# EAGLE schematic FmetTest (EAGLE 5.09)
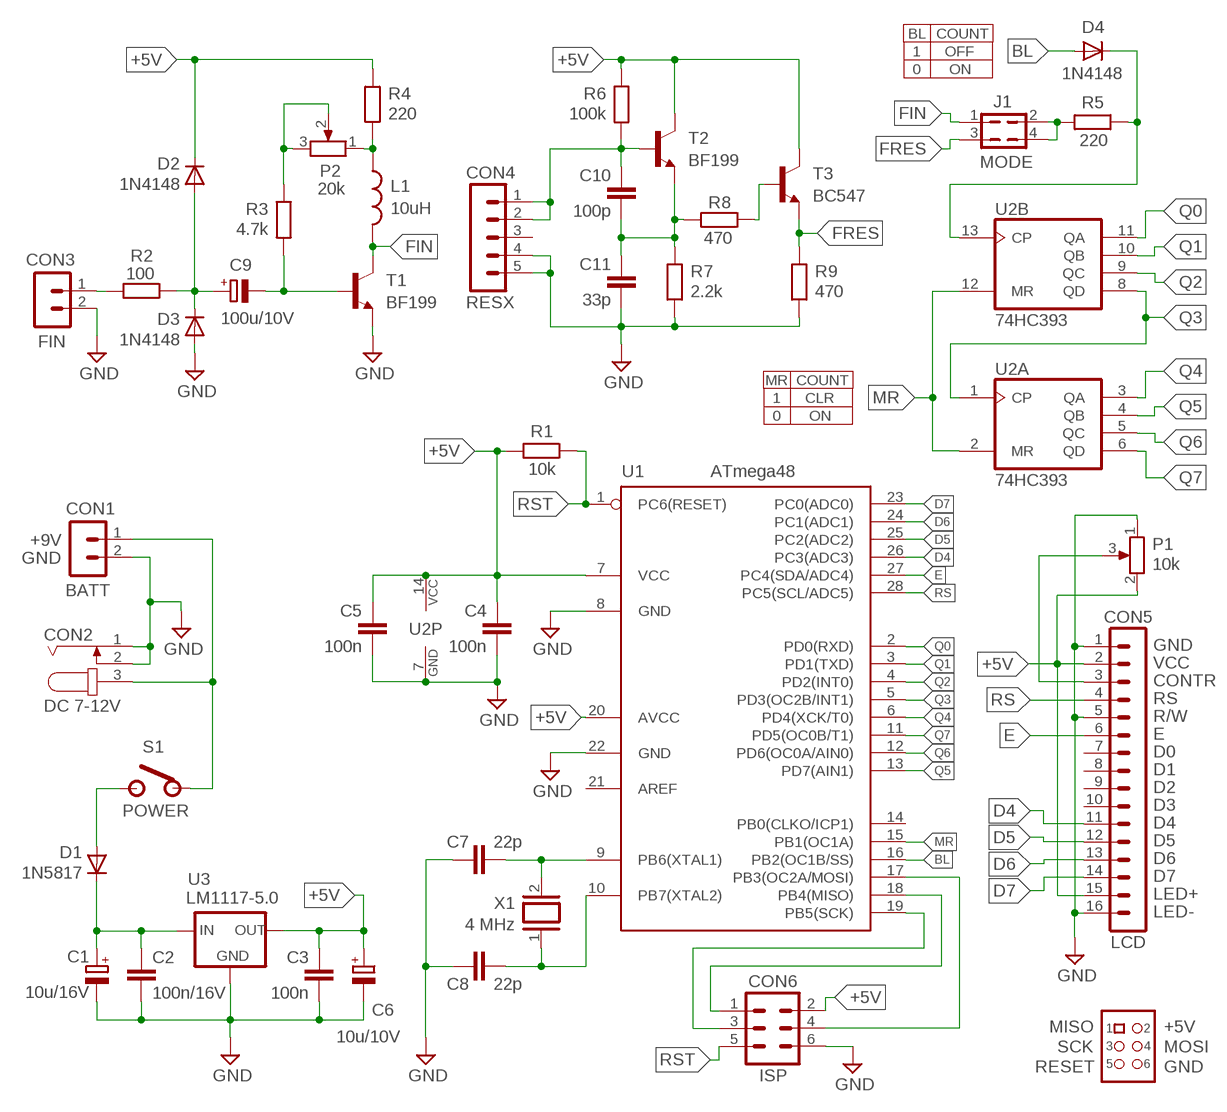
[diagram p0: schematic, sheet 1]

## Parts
C1  10u/16V  C5/2.5  [C5/2.5]
C2  100n/16V  C5-025X075  [C5-025X075]
C3  100n  C5-025X075  [C5-025X075]
C4  100n  C5-025X075  [C5-025X075]
C5  100n  C5-025X075  [C5-025X075]
C6  10u/10V  C5/2.5  [C5/2.5]
C7  22p  C5-025X075  [C5-025X075]
C8  22p  C5-025X075  [C5-025X075]
C9  100u/10V  C7/2.5  [C7/2.5]
C10  100p  C5-025X075  [C5-025X075]
C11  33p  C5-025X075  [C5-025X075]
CON1  BATT  CON-2PIN  [CON-2PIN]
CON2  DC 7-12V  DC-JACK  [DC-JACK]
CON3  FIN  CON-2PIN  [CON-2PIN]
CON4  RESX  CON-5X1  [CON-5X1]
CON5  LCD  CON-16X1  [CON-16X1]
CON6  ISP  CON-3X2  [CON-3X2]
D1  1N5817  PAD-D7.5N  [D-7.5]
D2  1N4148  PAD-D7.5S  [D-7]
D3  1N4148  PAD-D7.5S  [D-7]
D4  1N4148  PAD-D7.5S  [D-7]
J1  MODE  J-2X2  [J-2X2]
L1  10uH  L5L7  [L7]
P1  10k  POT5X5V  [POT5X5V]
P2  20k  P-HELITRIM  [P-HV]
R1  10k  R10R7  [R7]
R2  100  R10R7  [R7]
R3  4.7k  R10R7  [R7]
R4  220  R10R7  [R7]
R5  220  R10R7  [R7]
R6  100k  R10R7  [R7]
R7  2.2k  R10R7  [R7]
R8  470  R10R7  [R7]
R9  470  R10R7  [R7]
S1  POWER  SW2A  [CON-2PIN]
T1  BF199  [TO92-CEB]
T2  BF199  [TO92-CEB]
T3  BC547  [TO92-CBE]
U1  ATmega48  ATMEGA48  [DIP28]
U2  74HC393  74393  [DIP14]
U3  LM1117-5.0  LM1117-FIX  [SOT223]
X1  4 MHz  XTAL  [XTAL]

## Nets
+5V: C3.1 C4.1 C5.1 C6.+ CON5.2 CON5.15 CON6.2 D2.C P1.2 R1.1 R4.2 R6.2 T2.C T3.C U1.7(VCC) U1.20(AVCC) U2.14(P:VCC) U3.2(OUT)
BL: D4.A
D4: CON5.11 U1.26(PC3(ADC3))
D5: CON5.12 U1.25(PC2(ADC2))
D6: CON5.13 U1.24(PC1(ADC1))
D7: CON5.14 U1.23(PC0(ADC0))
E: CON5.6 U1.27(PC4(SDA/ADC4))
FIN: J1.1 L1.2 T1.C
FRES: J1.3 R9.2 T3.E
GND: C1.- C2.2 C3.2 C4.2 C5.2 C6.- C7.1 C8.1 C11.2 CON1.2 CON2.1 CON2.2 CON3.2 CON4.4 CON4.5 CON5.1 CON5.5 CON5.16 CON6.6 D3.A P1.1 R7.1 R9.1 T1.E U1.8(GND) U1.22(GND) U2.7(P:GND) U3.1(GND)
MR: U2.2(A:MR) U2.12(B:MR)
N$1: D1.A S1.1
N$3: CON3.1 R2.1
N$4: C7.2 U1.9(PB6(XTAL1)) X1.2
N$6: C9.+ D2.A D3.C R2.2
N$7: C8.2 U1.10(PB7(XTAL2)) X1.1
N$8: R8.2 T3.B
N$9: C9.- R3.1 T1.B
N$10: P2.2 P2.3 R3.2
N$13: L1.1 P2.1 R4.1
N$15: J1.2 J1.4 R5.1
N$16: C10.2 C11.1 R7.2 R8.1 T2.E
N$17: C10.1 CON4.1 CON4.2 R6.1 T2.B
N$18: D4.C R5.2 U2.13(B:CP)
N$26: CON1.1 CON2.3 S1.2
N$34: CON5.3 P1.3
N$48: CON6.4 U1.17(PB3(OC2A/MOSI))
N$51: CON6.1 U1.18(PB4(MISO))
N$53: CON6.3 U1.19(PB5(SCK))
Q0: U1.2(PD0(RXD)) U2.11(B:QA)
Q1: U1.3(PD1(TXD)) U2.10(B:QB)
Q2: U1.4(PD2(INT0)) U2.9(B:QC)
Q3: U1.5(PD3(OC2B/INT1)) U2.1(A:CP) U2.8(B:QD)
Q4: U1.6(PD4(XCK/T0)) U2.3(A:QA)
Q5: U1.13(PD7(AIN1)) U2.4(A:QB)
Q6: U1.12(PD6(OC0A/AIN0)) U2.5(A:QC)
Q7: U1.11(PD5(OC0B/T1)) U2.6(A:QD)
RS: CON5.4 U1.28(PC5(SCL/ADC5))
RST: CON6.5 R1.2 U1.1(PC6(RESET))
VCC: C1.+ C2.1 D1.C U3.3(IN)
Unconnected: CON4.3 CON5.7 CON5.8 CON5.9 CON5.10 U1.14(PB0(CLKO/ICP1)) U1.15(PB1(OC1A)) U1.16(PB2(OC1B/SS)) U1.21(AREF)

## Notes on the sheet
- BL | COUNT
- 1 | OFF
- 0 | ON
- MR | COUNT
- 1 | CLR
- 0 | ON
- +9V
- GND
- GND
- VCC
- CONTR
- RS
- R/W
- E
- D0
- D1
- D2
- D3
- D4
- D5
- D6
- D7
- LED+
- LED-
- MISO | 1 | 2 | +5V
- SCK | 3 | 4 | MOSI
- 5 | 6
- RESET | GND

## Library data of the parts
C1 C6 = _my:C5/2.5
C2-C5 C7 C8 C10 C11 = _my:C5-025X075
C9 = _my:C7/2.5
CON1 CON3 = _my:CON-2PIN
CON2 = _my:DC-JACK
CON4 = _my:CON-5X1
CON5 = _my:CON-16X1
CON6 = _my:CON-3X2
D1-D4 = _my:PAD-D7.5
J1 = _my:J-2X2
L1 = _my:L5
P1 = _my:POT5X5
P2 = _my:P-HELITRIM
R1-R9 = _my:R10
S1 = _my:SW2A
T1 T2 = _my:BF199
T3 = _my:BC547
U1 = _my:ATMEGA48
U2 = _my:74393
U3 = _my:LM1117-FIX
X1 = _my:XTAL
